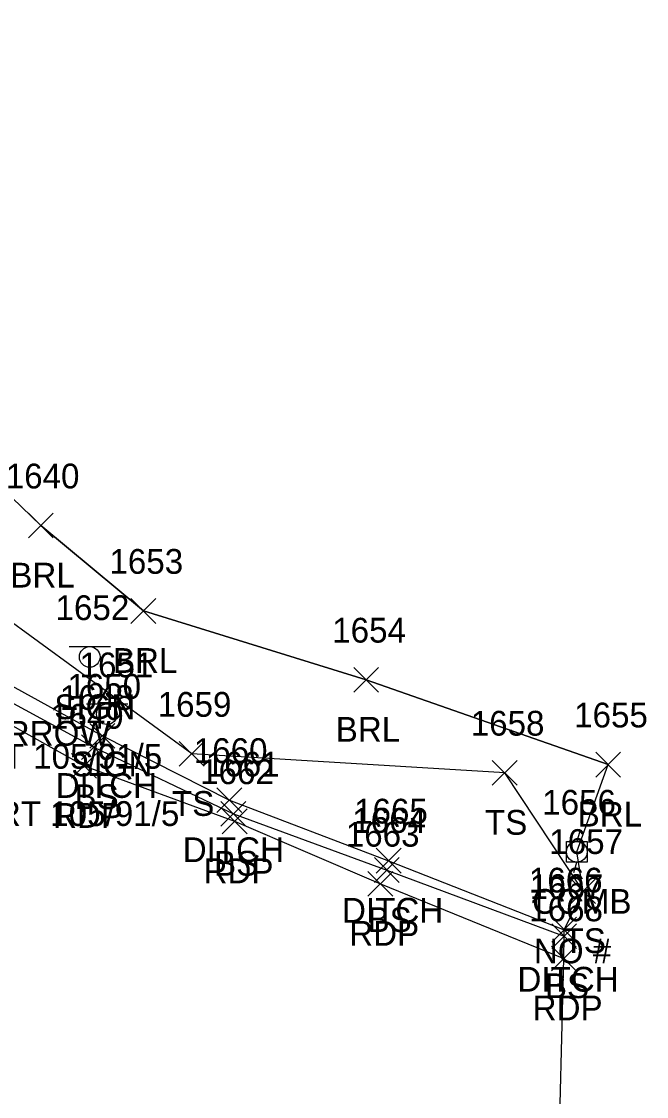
# Model space of a CAD drawing. Extents: x 1716490 to 1717645, y 888034 to 890004.
# Drawn here: x 1717585.7 to 1717636.1, y 888284.2 to 888370.9 of the extents above; entities that cross this region are included whole.
import ezdxf

# ---------------------------------------------------------------- set-up
doc = ezdxf.new("R2010")
doc.units = 0
for name, color, linetype in [('D_A', 7, 'Continuous'), ('D_I', 7, 'Continuous'), ('D_TIC', 7, 'Continuous'), ('DD', 7, 'Continuous'), ('L_A', 7, 'Continuous'), ('L_I', 7, 'Continuous'), ('L_TIC', 7, 'Continuous'), ('LABL', 7, 'Continuous'), ('LELB', 7, 'Continuous'), ('LSOGP', 7, 'Continuous'), ('P_A', 7, 'Continuous'), ('P_I', 7, 'Continuous'), ('P_TIC', 7, 'Continuous'), ('PET', 7, 'Continuous'), ('S_A', 7, 'Continuous'), ('S_C', 7, 'Continuous'), ('S_I', 7, 'Continuous'), ('SSGN', 7, 'Continuous'), ('U_A', 7, 'Continuous'), ('U_C', 7, 'Continuous'), ('U_I', 7, 'Continuous'), ('UP', 7, 'Continuous')]:
    doc.layers.add(name, color=color, linetype=linetype)

msp = doc.modelspace()

# ---------------------------------------------------------------- linework, layer by layer
at = {"layer": 'D_TIC'}
for points in [[(1717591.254, 888312.277), (1717593.254, 888314.277)], [(1717593.254, 888312.277), (1717591.254, 888314.277)], [(1717601.5, 888307.091), (1717603.5, 888309.091)], [(1717603.5, 888307.091), (1717601.5, 888309.091)], [(1717614.345, 888302.206), (1717616.345, 888304.206)], [(1717616.345, 888302.206), (1717614.345, 888304.206)], [(1717628.497, 888296.638), (1717630.497, 888298.638)], [(1717630.497, 888296.638), (1717628.497, 888298.638)]]:
    msp.add_lwpolyline(points, dxfattribs=at)
at = {"layer": 'DD'}
msp.add_lwpolyline([(1717555.508, 888338.303), (1717558.291, 888337.535), (1717560.604, 888334.718), (1717566.96, 888328.068), (1717580.72, 888319.627), (1717592.254, 888313.277), (1717602.5, 888308.091), (1717615.345, 888303.206), (1717629.497, 888297.638)], dxfattribs=at)
at = {"layer": 'L_TIC'}
for points in [[(1717586.285, 888329.255), (1717588.285, 888331.255)], [(1717588.285, 888329.255), (1717586.285, 888331.255)], [(1717594.562, 888322.364), (1717596.562, 888324.364)], [(1717596.562, 888322.364), (1717594.562, 888324.364)], [(1717612.533, 888316.811), (1717614.533, 888318.811)], [(1717614.533, 888316.811), (1717612.533, 888318.811)], [(1717590.565, 888311.374), (1717592.565, 888313.374)], [(1717592.565, 888311.374), (1717590.565, 888313.374)], [(1717598.462, 888310.824), (1717600.462, 888312.824)], [(1717600.462, 888310.824), (1717598.462, 888312.824)], [(1717632.047, 888309.962), (1717634.047, 888311.962)], [(1717634.047, 888309.962), (1717632.047, 888311.962)], [(1717623.706, 888309.302), (1717625.706, 888311.302)], [(1717625.706, 888309.302), (1717623.706, 888311.302)], [(1717601.82, 888305.996), (1717603.82, 888307.996)], [(1717603.82, 888305.996), (1717601.82, 888307.996)], [(1717614.199, 888301.454), (1717616.199, 888303.454)], [(1717616.199, 888301.454), (1717614.199, 888303.454)], [(1717630.044, 888299.75), (1717632.044, 888301.75)], [(1717632.044, 888299.75), (1717630.044, 888301.75)], [(1717628.508, 888296.112), (1717630.508, 888298.112)], [(1717630.508, 888296.112), (1717628.508, 888298.112)]]:
    msp.add_lwpolyline(points, dxfattribs=at)
at = {"layer": 'LABL'}
msp.add_lwpolyline([(1717560.486, 888368.617), (1717564.075, 888359.641), (1717562.302, 888349.072), (1717562.955, 888341.795), (1717569.217, 888339.223), (1717579.539, 888337.707), (1717587.285, 888330.255), (1717595.562, 888323.364), (1717613.533, 888317.811), (1717633.047, 888310.962)], dxfattribs=at)
at = {"layer": 'LELB'}
for points in [[(1717544.903, 888369.017), (1717548.168, 888359.084), (1717550.496, 888350.917), (1717553.592, 888343.785), (1717555.508, 888338.303), (1717556.124, 888337.629), (1717564.486, 888328.534), (1717573.667, 888322.272), (1717582.002, 888317.572), (1717591.565, 888312.374), (1717602.82, 888306.996), (1717615.199, 888302.454), (1717629.508, 888297.112)], [(1717631.044, 888300.75), (1717624.706, 888310.302), (1717599.462, 888311.824), (1717580.893, 888325.382), (1717576.422, 888329.506)]]:
    msp.add_lwpolyline(points, dxfattribs=at)
at = {"layer": 'LSOGP'}
msp.add_lwpolyline([(1717629.031, 888277.17), (1717629.472, 888295.319), (1717629.508, 888297.112), (1717629.497, 888297.638), (1717631.044, 888300.75), (1717630.527, 888303.919), (1717633.047, 888310.962), (1717613.533, 888317.811), (1717595.562, 888323.364), (1717587.285, 888330.255), (1717579.539, 888337.707), (1717569.896, 888338.32), (1717569.217, 888339.223), (1717562.302, 888349.072), (1717564.075, 888359.641), (1717560.486, 888368.617), (1717546.752, 888369.431), (1717544.903, 888369.017), (1717542.72, 888367.847), (1717522.623, 888364.733), (1717495.012, 888370.943)], dxfattribs=at)
at = {"layer": 'P_TIC'}
for points in [[(1717589.778, 888309.857), (1717591.778, 888311.857)], [(1717591.778, 888309.857), (1717589.778, 888311.857)], [(1717601.926, 888305.386), (1717603.926, 888307.386)], [(1717603.926, 888305.386), (1717601.926, 888307.386)], [(1717613.676, 888300.341), (1717615.676, 888302.341)], [(1717615.676, 888300.341), (1717613.676, 888302.341)], [(1717628.472, 888294.319), (1717630.472, 888296.319)], [(1717630.472, 888294.319), (1717628.472, 888296.319)]]:
    msp.add_lwpolyline(points, dxfattribs=at)
at = {"layer": 'PET'}
msp.add_lwpolyline([(1717542.72, 888367.847), (1717546.561, 888358.26), (1717548.72, 888350.179), (1717551.225, 888343.942), (1717554.298, 888338.081), (1717559.467, 888331.229), (1717565.615, 888325.787), (1717579.394, 888317.231), (1717590.778, 888310.857), (1717602.926, 888306.386), (1717614.676, 888301.341), (1717629.472, 888295.319)], dxfattribs=at)
at = {"layer": 'SSGN'}
for p, q in [((1717589.589, 888320.483), (1717592.922, 888320.483)), ((1717591.236, 888319.65), (1717591.236, 888319.65)), ((1717590.966, 888315.864), (1717594.299, 888315.864)), ((1717592.613, 888315.031), (1717592.613, 888315.031))]:
    msp.add_line(p, q, dxfattribs=at)
for centre in [(1717591.236, 888319.65), (1717592.613, 888315.031)]:
    msp.add_circle(centre, 0.833, dxfattribs=at)
at = {"layer": 'UP'}
for p, q in [((1717630.777, 888305.586), (1717630.527, 888304.753)), ((1717629.694, 888303.086), (1717629.694, 888304.753)), ((1717629.694, 888304.753), (1717631.361, 888304.753)), ((1717631.361, 888304.753), (1717631.361, 888303.086)), ((1717630.527, 888303.919), (1717630.527, 888303.919)), ((1717631.361, 888303.086), (1717629.694, 888303.086)), ((1717630.277, 888302.253), (1717630.527, 888303.086))]:
    msp.add_line(p, q, dxfattribs=at)
msp.add_circle((1717630.527, 888303.919), 0.833, dxfattribs=at)

# ---------------------------------------------------------------- texts
at = {"layer": 'D_A'}
for p in [(1717588.49, 888308.277), (1717598.736, 888303.091), (1717611.581, 888298.206), (1717625.734, 888292.638)]:
    msp.add_text('DITCH', height=2, dxfattribs=at).set_placement(p)
at = {"layer": 'D_I'}
for s, p in [('1650', (1717589.427, 888316.277)), ('1660', (1717599.626, 888311.091)), ('1665', (1717612.558, 888306.206)), ('1666', (1717626.655, 888300.638))]:
    msp.add_text(s, height=2, dxfattribs=at).set_placement(p)
at = {"layer": 'L_A'}
for s, p in [('BRL', (1717584.828, 888325.255)), ('BRL', (1717593.105, 888318.364)), ('BRL', (1717611.076, 888312.811)), ('BS', (1717590.006, 888307.374)), ('TS', (1717597.871, 888306.824)), ('BRL', (1717630.591, 888305.962)), ('TS', (1717623.116, 888305.302)), ('BS', (1717601.261, 888301.996)), ('BS', (1717613.64, 888297.454)), ('TS', (1717629.453, 888295.75)), ('BS', (1717627.949, 888292.112))]:
    msp.add_text(s, height=2, dxfattribs=at).set_placement(p)
at = {"layer": 'L_I'}
for s, p in [('1640', (1717584.458, 888333.255)), ('1653', (1717592.822, 888326.364)), ('1654', (1717610.793, 888320.811)), ('1648', (1717588.825, 888315.374)), ('1659', (1717596.714, 888314.824)), ('1658', (1717621.966, 888313.302)), ('1655', (1717630.307, 888313.962)), ('1661', (1717600.599, 888309.996)), ('1664', (1717612.412, 888305.454)), ('1657', (1717628.304, 888303.75)), ('1667', (1717626.72, 888300.112))]:
    msp.add_text(s, height=2, dxfattribs=at).set_placement(p)
at = {"layer": 'P_A'}
for p in [(1717588.266, 888305.857), (1717600.414, 888301.386), (1717612.165, 888296.341), (1717626.96, 888290.319)]:
    msp.add_text('RDP', height=2, dxfattribs=at).set_placement(p)
at = {"layer": 'P_I'}
for s, p in [('1649', (1717588.03, 888313.857)), ('1662', (1717600.138, 888309.386)), ('1663', (1717611.889, 888304.341)), ('1668', (1717626.685, 888298.319))]:
    msp.add_text(s, height=2, dxfattribs=at).set_placement(p)
at = {"layer": 'S_A'}
for p in [(1717588.374, 888314.629), (1717589.751, 888310.011)]:
    msp.add_text('SIGN', height=2, dxfattribs=at).set_placement(p)
at = {"layer": 'S_C'}
for s, p in [('CAUTION ARROW', (1717569.897, 888312.491)), ('RT 105/91/5', (1717582.366, 888310.629)), ('RT 105/91/5', (1717583.743, 888306.011))]:
    msp.add_text(s, height=2, dxfattribs=at).set_placement(p)
at = {"layer": 'S_I'}
for s, p in [('1652', (1717588.476, 888322.629)), ('1651', (1717590.42, 888318.011))]:
    msp.add_text(s, height=2, dxfattribs=at).set_placement(p)
at = {"layer": 'U_A'}
msp.add_text('COMB', height=2, dxfattribs=at).set_placement((1717626.913, 888298.919))
at = {"layer": 'U_C'}
msp.add_text('NO #', height=2, dxfattribs=at).set_placement((1717627.063, 888294.919))
at = {"layer": 'U_I'}
msp.add_text('1656', height=2, dxfattribs=at).set_placement((1717627.732, 888306.919))

doc.saveas('drawing.dxf')
